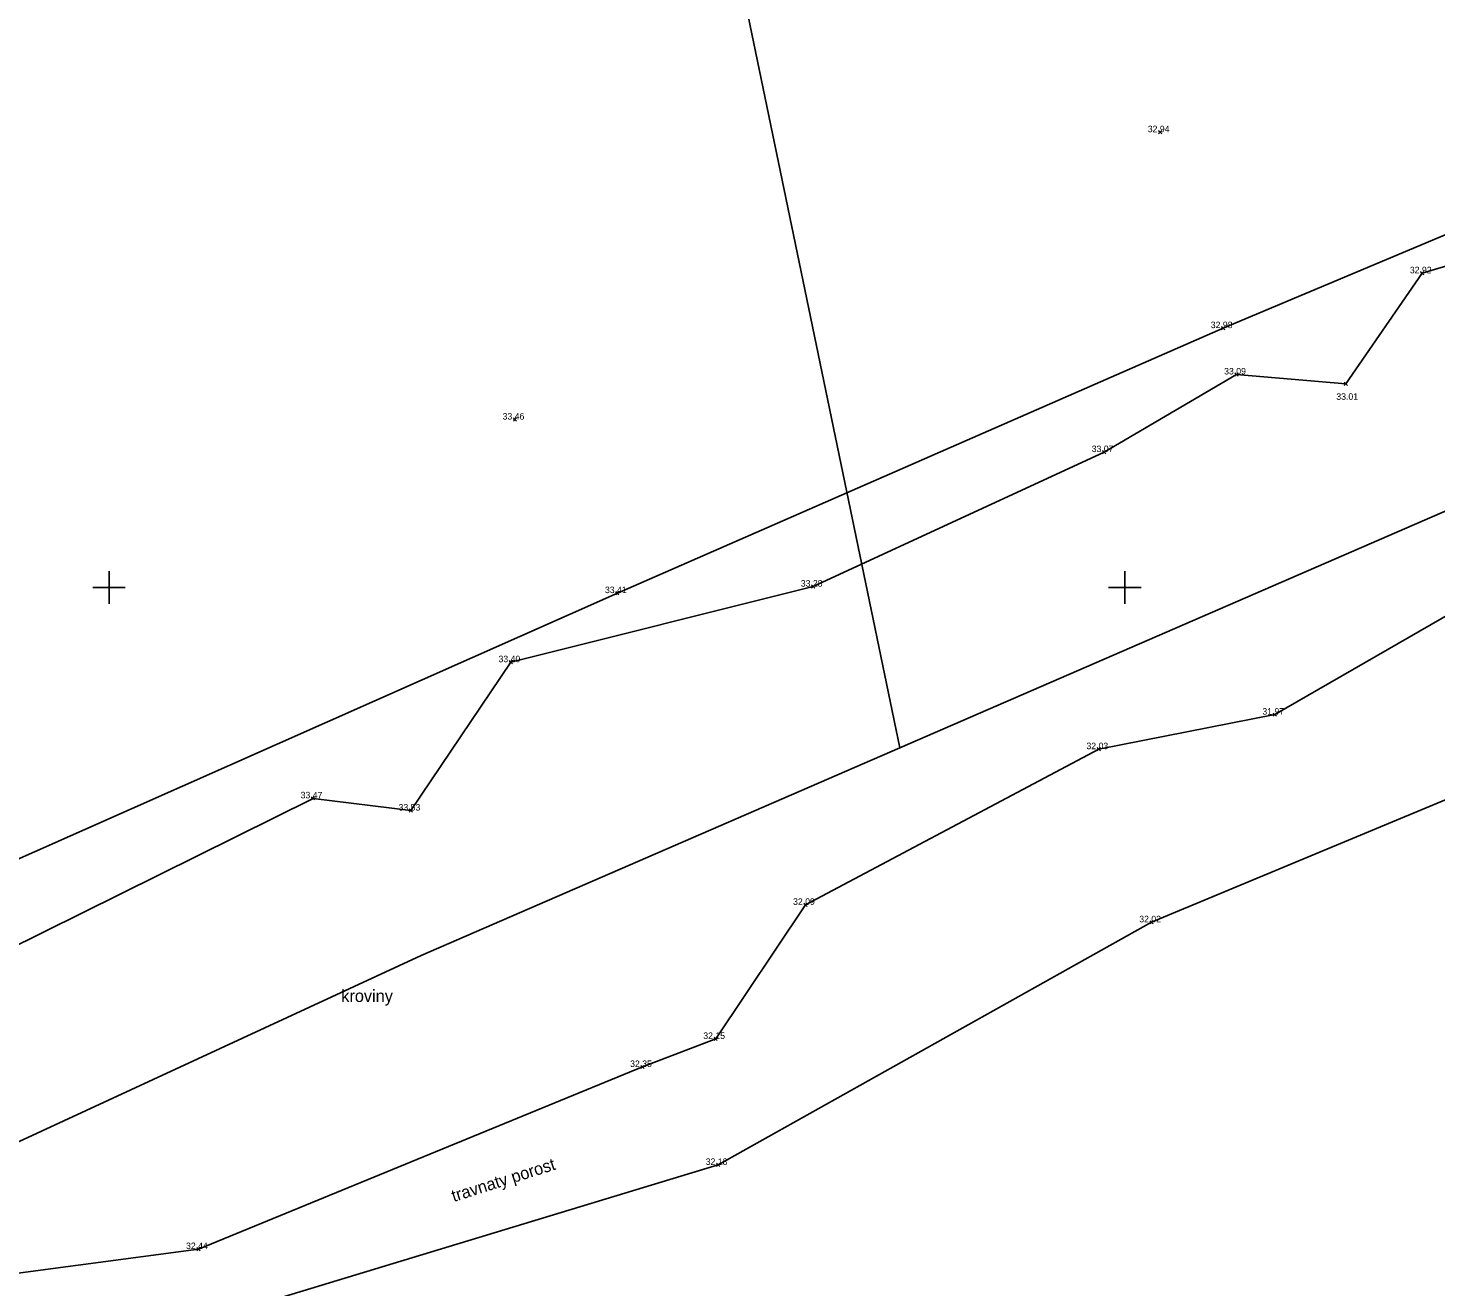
# Model space of a CAD drawing. Extents: x -772865 to -772533, y -1034366 to -1034132.
# Drawn here: x -772701.99 to -772667.35, y -1034242.21 to -1034211.24 of the extents above; entities that cross this region are included whole.
import ezdxf

# ---------------------------------------------------------------- set-up
doc = ezdxf.new("R2010")
doc.units = 0
for name, color, linetype in [('body', 7, 'Continuous'), ('KM_hranice', 7, 'Continuous'), ('mistni_popis', 7, 'Continuous'), ('oddeleni_ploch', 7, 'Continuous'), ('souradnicova_sit', 7, 'Continuous'), ('stromy_kere', 7, 'Continuous'), ('vyskove_koty', 7, 'Continuous')]:
    doc.layers.add(name, color=color, linetype=linetype)

msp = doc.modelspace()

# ---------------------------------------------------------------- linework, layer by layer
at = {"layer": 'body'}
for p, q in [((-772674.09, -1034213.84), (-772674.17, -1034213.76)), ((-772674.17, -1034213.84), (-772674.09, -1034213.76)), ((-772667.64, -1034217.31), (-772667.72, -1034217.23)), ((-772667.72, -1034217.31), (-772667.64, -1034217.23)), ((-772672.54, -1034218.66), (-772672.62, -1034218.58)), ((-772672.62, -1034218.66), (-772672.54, -1034218.58)), ((-772672.21, -1034219.8), (-772672.29, -1034219.72)), ((-772672.29, -1034219.8), (-772672.21, -1034219.72)), ((-772669.52, -1034220.03), (-772669.6, -1034219.95)), ((-772669.6, -1034220.03), (-772669.52, -1034219.95)), ((-772689.97, -1034220.91), (-772690.05, -1034220.83)), ((-772690.05, -1034220.91), (-772689.97, -1034220.83)), ((-772675.47, -1034221.71), (-772675.55, -1034221.63)), ((-772675.55, -1034221.71), (-772675.47, -1034221.63)), ((-772687.45, -1034225.18), (-772687.53, -1034225.1)), ((-772687.53, -1034225.18), (-772687.45, -1034225.1)), ((-772682.63, -1034225.02), (-772682.71, -1034224.94)), ((-772682.71, -1034225.02), (-772682.63, -1034224.94)), ((-772690.07, -1034226.88), (-772690.15, -1034226.8)), ((-772690.15, -1034226.88), (-772690.07, -1034226.8)), ((-772671.27, -1034228.17), (-772671.35, -1034228.09)), ((-772671.35, -1034228.17), (-772671.27, -1034228.09)), ((-772675.6, -1034229.02), (-772675.68, -1034228.94)), ((-772675.68, -1034229.02), (-772675.6, -1034228.94)), ((-772694.94, -1034230.23), (-772695.02, -1034230.15)), ((-772695.02, -1034230.23), (-772694.94, -1034230.15)), ((-772692.53, -1034230.53), (-772692.61, -1034230.45)), ((-772692.61, -1034230.53), (-772692.53, -1034230.45)), ((-772682.82, -1034232.85), (-772682.9, -1034232.77)), ((-772682.9, -1034232.85), (-772682.82, -1034232.77)), ((-772674.3, -1034233.28), (-772674.38, -1034233.2)), ((-772674.38, -1034233.28), (-772674.3, -1034233.2)), ((-772685.03, -1034236.15), (-772685.11, -1034236.07)), ((-772685.11, -1034236.15), (-772685.03, -1034236.07)), ((-772686.83, -1034236.84), (-772686.91, -1034236.76)), ((-772686.91, -1034236.84), (-772686.83, -1034236.76)), ((-772684.97, -1034239.25), (-772685.05, -1034239.17)), ((-772685.05, -1034239.25), (-772684.97, -1034239.17)), ((-772697.76, -1034241.32), (-772697.84, -1034241.24)), ((-772697.84, -1034241.32), (-772697.76, -1034241.24))]:
    msp.add_line(p, q, dxfattribs=at)
at = {"layer": 'KM_hranice'}
for p, q in [((-772698.71, -1034141.14), (-772680.54, -1034228.95)), ((-772656.67, -1034218.59), (-772680.54, -1034228.95)), ((-772680.54, -1034228.95), (-772692.32, -1034234.06)), ((-772692.32, -1034234.06), (-772741, -1034256.54))]:
    msp.add_line(p, q, dxfattribs=at)
at = {"layer": 'oddeleni_ploch'}
for points in [[(-772574.1, -1034196.14), (-772586.87, -1034201.34), (-772598.23, -1034205.06), (-772614.53, -1034207.42), (-772626.93, -1034206.95), (-772636.66, -1034207.26), (-772647.96, -1034208.36), (-772659.39, -1034213.08), (-772672.58, -1034218.62), (-772687.49, -1034225.14), (-772703.01, -1034232.02), (-772714.35, -1034236.9), (-772728.88, -1034243.07), (-772737.97, -1034245.74), (-772746.8, -1034246.99), (-772753.85, -1034250.11), (-772762.71, -1034257.3), (-772782.05, -1034269.18), (-772797.09, -1034276.39), (-772810.61, -1034282.39), (-772816.13, -1034284.08), (-772822.76, -1034283.4), (-772826.73, -1034280.27)], [(-772569.67, -1034207.72), (-772578.35, -1034211.18), (-772588.33, -1034216.15), (-772592.11, -1034217.46), (-772598.89, -1034219.1), (-772610.21, -1034219.57), (-772621.14, -1034219.48), (-772637.34, -1034221.06), (-772647.54, -1034222.08), (-772674.34, -1034233.24), (-772685.01, -1034239.21), (-772697.33, -1034242.95), (-772712.12, -1034249.56), (-772725.85, -1034254.8), (-772738.85, -1034261.98), (-772750.37, -1034267.76), (-772764, -1034272.65), (-772783.9, -1034280.59), (-772796.38, -1034286.28), (-772810.31, -1034291.67), (-772823.61, -1034294.35), (-772828.52, -1034296.12), (-772827.01, -1034302.81), (-772823.23, -1034300.75)]]:
    msp.add_lwpolyline(points, dxfattribs=at)
at = {"layer": 'souradnicova_sit'}
for p, q in [((-772700, -1034224.6), (-772700, -1034225.4)), ((-772675, -1034224.6), (-772675, -1034225.4)), ((-772700.4, -1034225), (-772699.6, -1034225)), ((-772675.4, -1034225), (-772674.6, -1034225))]:
    msp.add_line(p, q, dxfattribs=at)
at = {"layer": 'stromy_kere'}
for points in [[(-772703.51, -1034234.42), (-772694.98, -1034230.19), (-772692.57, -1034230.49), (-772690.11, -1034226.84), (-772682.67, -1034224.98), (-772675.51, -1034221.67), (-772672.25, -1034219.76), (-772669.56, -1034219.99), (-772667.68, -1034217.27), (-772659.65, -1034214.88), (-772652.01, -1034211.79), (-772645.15, -1034209.57), (-772641.61, -1034208.89), (-772633.71, -1034210.15), (-772627.94, -1034210.51), (-772625.02, -1034208.48), (-772619.49, -1034209.69), (-772612.97, -1034209.94), (-772600.85, -1034207.82), (-772593.5, -1034206.2), (-772588.67, -1034204.86)], [(-772583.42, -1034211.72), (-772590.3, -1034214.78), (-772599.43, -1034217.31), (-772610.6, -1034216.68), (-772621.69, -1034215.38), (-772638.07, -1034215.85), (-772648.66, -1034218.46), (-772661.39, -1034222.42), (-772671.31, -1034228.13), (-772675.64, -1034228.98), (-772682.86, -1034232.81), (-772685.07, -1034236.11), (-772686.87, -1034236.8), (-772697.8, -1034241.28), (-772703.73, -1034242.07)]]:
    msp.add_lwpolyline(points, dxfattribs=at)

# ---------------------------------------------------------------- texts
at = {"layer": 'mistni_popis'}
msp.add_text('kroviny', height=0.3, dxfattribs=at).set_placement((-772694.285, -1034235.2))
msp.add_text('travnaty porost', height=0.3, rotation=17.7044, dxfattribs=at).set_placement((-772691.516, -1034240.124))
at = {"layer": 'vyskove_koty'}
for s, p in [('32.94', (-772674.435, -1034213.8)), ('32.92', (-772667.985, -1034217.27)), ('32.98', (-772672.885, -1034218.62)), ('33.09', (-772672.555, -1034219.76)), ('33.01', (-772669.795, -1034220.384)), ('33.46', (-772690.315, -1034220.87)), ('33.07', (-772675.815, -1034221.67)), ('33.41', (-772687.795, -1034225.14)), ('33.28', (-772682.975, -1034224.98)), ('33.40', (-772690.415, -1034226.84)), ('31.97', (-772671.615, -1034228.13)), ('32.03', (-772675.945, -1034228.98)), ('33.47', (-772695.285, -1034230.19)), ('33.53', (-772692.875, -1034230.49)), ('32.09', (-772683.165, -1034232.81)), ('32.02', (-772674.645, -1034233.24)), ('32.15', (-772685.375, -1034236.11)), ('32.35', (-772687.175, -1034236.8)), ('32.18', (-772685.315, -1034239.21)), ('32.44', (-772698.105, -1034241.28))]:
    msp.add_text(s, height=0.16, dxfattribs=at).set_placement(p)

doc.saveas('drawing.dxf')
